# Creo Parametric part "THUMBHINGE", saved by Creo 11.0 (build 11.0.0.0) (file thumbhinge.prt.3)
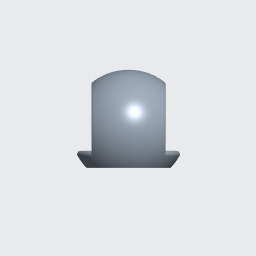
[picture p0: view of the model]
Units: Inch lbm Second (Pro/E Default); INCH, POUND, SECS

Created from: XX_INLBS_PART_SOLID_ABS.PRT

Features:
  1. datum plane "RIGHT"
  2. datum plane "TOP"
  3. datum plane "FRONT"
  4. coordinate system
  5. sketch "Sketch 1", "A_1"
  6. revolve "Revolve 1"
  7. datum plane "DTM1"
  8. sketch "Sketch 2"
  9. extruded cut "Extrude 1"
  10. mirror "Mirror 1"
  11. extruded cut "Extrude 1 (2)"
  12. round "Round 1"
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
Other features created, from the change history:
  sketch "Sketch 3"
  extruded cut "Extrude 2"
  datum plane "DTM2"
  datum plane "DTM3"
  sketch "Sketch 4"
  extruded cut "Extrude 3"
